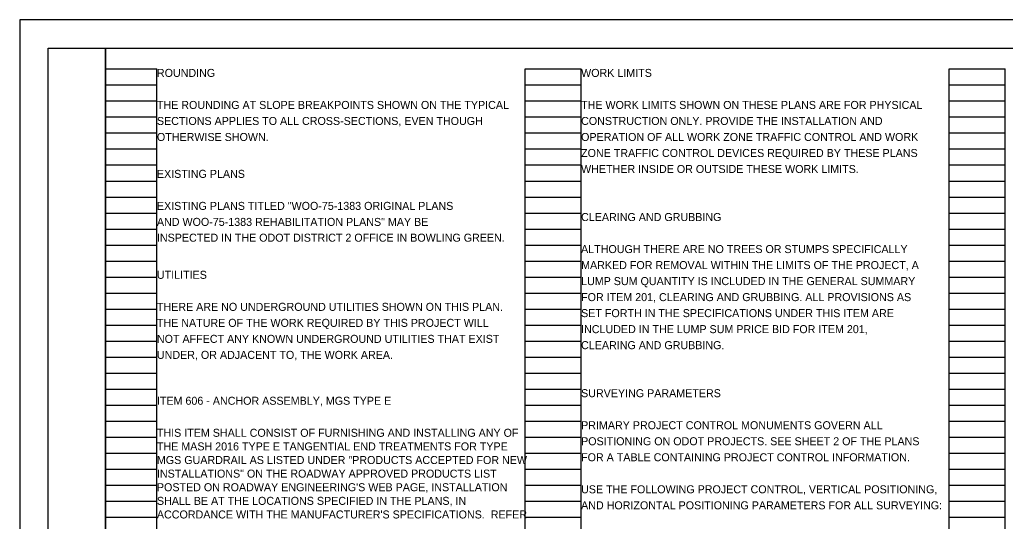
# Model space of a CAD drawing. Extents: x -19.6 to 34, y -1.8 to 22.
# Drawn here: x 0 to 17.24, y 13.23 to 22 of the extents above; entities that cross this region are included whole.
import ezdxf

# ---------------------------------------------------------------- set-up
doc = ezdxf.new("R2010")
doc.units = 0
for name, color, linetype in [('SH_Border', 7, 'Continuous'), ('SH_Cut_Line', 7, 'Continuous'), ('SH_Data', 7, 'Continuous'), ('SH_Text', 7, 'Continuous')]:
    doc.layers.add(name, color=color, linetype=linetype)

msp = doc.modelspace()

# ---------------------------------------------------------------- linework, layer by layer
at = {"layer": 'SH_Border'}
msp.add_lwpolyline([(0, 0), (34, 0), (34, 22), (0, 22)], close=True, dxfattribs=at)
at = {"layer": 'SH_Cut_Line'}
for points in [[(0.5, 21.5), (1.5, 21.5), (1.5, 0.5), (0.5, 0.5)], [(1.5, 21.5), (33.5, 21.5), (33.5, 0.5), (1.5, 0.5)]]:
    msp.add_lwpolyline(points, close=True, dxfattribs=at)
at = {"layer": 'SH_Data'}
for p, q in [((1.5, 0.98), (1.5, 21.14)), ((1.5, 21.14), (2.4, 21.14)), ((2.4, 0.98), (2.4, 21.14)), ((8.84, 0.98), (8.84, 21.14)), ((8.84, 21.14), (9.82, 21.14)), ((9.82, 0.98), (9.82, 21.14)), ((16.26, 0.98), (16.26, 21.14)), ((16.26, 21.14), (17.24, 21.14)), ((17.24, 0.98), (17.24, 21.14)), ((1.5, 20.86), (2.4, 20.86)), ((8.84, 20.86), (9.82, 20.86)), ((16.26, 20.86), (17.24, 20.86)), ((1.5, 20.58), (2.4, 20.58)), ((8.84, 20.58), (9.82, 20.58)), ((16.26, 20.58), (17.24, 20.58)), ((1.5, 20.3), (2.4, 20.3)), ((8.84, 20.3), (9.82, 20.3)), ((16.26, 20.3), (17.24, 20.3)), ((1.5, 20.02), (2.4, 20.02)), ((8.84, 20.02), (9.82, 20.02)), ((16.26, 20.02), (17.24, 20.02)), ((1.5, 19.74), (2.4, 19.74)), ((8.84, 19.74), (9.82, 19.74)), ((16.26, 19.74), (17.24, 19.74)), ((1.5, 19.46), (2.4, 19.46)), ((8.84, 19.46), (9.82, 19.46)), ((16.26, 19.46), (17.24, 19.46)), ((1.5, 19.18), (2.4, 19.18)), ((8.84, 19.18), (9.82, 19.18)), ((16.26, 19.18), (17.24, 19.18)), ((1.5, 18.9), (2.4, 18.9)), ((8.84, 18.9), (9.82, 18.9)), ((16.26, 18.9), (17.24, 18.9)), ((1.5, 18.62), (2.4, 18.62)), ((8.84, 18.62), (9.82, 18.62)), ((16.26, 18.62), (17.24, 18.62)), ((1.5, 18.34), (2.4, 18.34)), ((8.84, 18.34), (9.82, 18.34)), ((16.26, 18.34), (17.24, 18.34)), ((1.5, 18.06), (2.4, 18.06)), ((8.84, 18.06), (9.82, 18.06)), ((16.26, 18.06), (17.24, 18.06)), ((1.5, 17.78), (2.4, 17.78)), ((8.84, 17.78), (9.82, 17.78)), ((16.26, 17.78), (17.24, 17.78)), ((1.5, 17.5), (2.4, 17.5)), ((8.84, 17.5), (9.82, 17.5)), ((16.26, 17.5), (17.24, 17.5)), ((1.5, 17.22), (2.4, 17.22)), ((8.84, 17.22), (9.82, 17.22)), ((16.26, 17.22), (17.24, 17.22)), ((1.5, 16.94), (2.4, 16.94)), ((8.84, 16.94), (9.82, 16.94)), ((16.26, 16.94), (17.24, 16.94)), ((1.5, 16.66), (2.4, 16.66)), ((8.84, 16.66), (9.82, 16.66)), ((16.26, 16.66), (17.24, 16.66)), ((1.5, 16.38), (2.4, 16.38)), ((8.84, 16.38), (9.82, 16.38)), ((16.26, 16.38), (17.24, 16.38)), ((1.5, 16.1), (2.4, 16.1)), ((8.84, 16.1), (9.82, 16.1)), ((16.26, 16.1), (17.24, 16.1)), ((1.5, 15.82), (2.4, 15.82)), ((8.84, 15.82), (9.82, 15.82)), ((16.26, 15.82), (17.24, 15.82)), ((1.5, 15.54), (2.4, 15.54)), ((8.84, 15.54), (9.82, 15.54)), ((16.26, 15.54), (17.24, 15.54)), ((1.5, 15.26), (2.4, 15.26)), ((8.84, 15.26), (9.82, 15.26)), ((16.26, 15.26), (17.24, 15.26)), ((1.5, 14.98), (2.4, 14.98)), ((8.84, 14.98), (9.82, 14.98)), ((16.26, 14.98), (17.24, 14.98)), ((1.5, 14.7), (2.4, 14.7)), ((8.84, 14.7), (9.82, 14.7)), ((16.26, 14.7), (17.24, 14.7)), ((1.5, 14.42), (2.4, 14.42)), ((8.84, 14.42), (9.82, 14.42)), ((16.26, 14.42), (17.24, 14.42)), ((1.5, 14.14), (2.4, 14.14)), ((8.84, 14.14), (9.82, 14.14)), ((16.26, 14.14), (17.24, 14.14)), ((1.5, 13.86), (2.4, 13.86)), ((8.84, 13.86), (9.82, 13.86)), ((16.26, 13.86), (17.24, 13.86)), ((1.5, 13.58), (2.4, 13.58)), ((8.84, 13.58), (9.82, 13.58)), ((16.26, 13.58), (17.24, 13.58)), ((1.5, 13.3), (2.4, 13.3)), ((8.84, 13.3), (9.82, 13.3)), ((16.26, 13.3), (17.24, 13.3))]:
    msp.add_line(p, q, dxfattribs=at)

# ---------------------------------------------------------------- texts
at = {"layer": 'SH_Text'}
for s, p in [('ROUNDING', (2.4, 21)), ('WORK LIMITS', (9.82, 21)), ('THE ROUNDING AT SLOPE BREAKPOINTS SHOWN ON THE TYPICAL', (2.4, 20.44)), ('THE WORK LIMITS SHOWN ON THESE PLANS ARE FOR PHYSICAL', (9.82, 20.44)), ('SECTIONS APPLIES TO ALL CROSS-SECTIONS, EVEN THOUGH', (2.4, 20.16)), ('CONSTRUCTION ONLY. PROVIDE THE INSTALLATION AND', (9.82, 20.16)), ('OTHERWISE SHOWN.', (2.4, 19.88)), ('OPERATION OF ALL WORK ZONE TRAFFIC CONTROL AND WORK', (9.82, 19.88)), ('ZONE TRAFFIC CONTROL DEVICES REQUIRED BY THESE PLANS', (9.82, 19.6)), ('EXISTING PLANS', (2.4, 19.235)), ('WHETHER INSIDE OR OUTSIDE THESE WORK LIMITS.', (9.82, 19.32)), ('EXISTING PLANS TITLED "WOO-75-1383 ORIGINAL PLANS', (2.4, 18.675)), ('CLEARING AND GRUBBING', (9.82, 18.48)), ('AND WOO-75-1383 REHABILITATION PLANS" MAY BE', (2.4, 18.395)), ('INSPECTED IN THE ODOT DISTRICT 2 OFFICE IN BOWLING GREEN.', (2.4, 18.119)), ('ALTHOUGH THERE ARE NO TREES OR STUMPS SPECIFICALLY', (9.82, 17.92)), ('MARKED FOR REMOVAL WITHIN THE LIMITS OF THE PROJECT, A', (9.82, 17.64)), ('UTILITIES', (2.4, 17.47)), ('LUMP SUM QUANTITY IS INCLUDED IN THE GENERAL SUMMARY', (9.82, 17.36)), ('FOR ITEM 201, CLEARING AND GRUBBING. ALL PROVISIONS AS', (9.82, 17.08)), ('THERE ARE NO UNDERGROUND UTILITIES SHOWN ON THIS PLAN.', (2.4, 16.91)), ('SET FORTH IN THE SPECIFICATIONS UNDER THIS ITEM ARE', (9.82, 16.8)), ('THE NATURE OF THE WORK REQUIRED BY THIS PROJECT WILL', (2.4, 16.63)), ('INCLUDED IN THE LUMP SUM PRICE BID FOR ITEM 201,', (9.82, 16.52)), ('NOT AFFECT ANY KNOWN UNDERGROUND UTILITIES THAT EXIST', (2.4, 16.35)), ('CLEARING AND GRUBBING.', (9.82, 16.24)), ('UNDER, OR ADJACENT TO, THE WORK AREA.', (2.4, 16.07)), ('SURVEYING PARAMETERS', (9.82, 15.4)), ('ITEM 606 - ANCHOR ASSEMBLY, MGS TYPE E', (2.4, 15.268)), ('THIS ITEM SHALL CONSIST OF FURNISHING AND INSTALLING ANY OF ', (2.4, 14.708)), ('PRIMARY PROJECT CONTROL MONUMENTS GOVERN ALL', (9.82, 14.84)), ('POSITIONING ON ODOT PROJECTS. SEE SHEET 2 OF THE PLANS', (9.82, 14.56)), ('THE MASH 2016 TYPE E TANGENTIAL END TREATMENTS FOR TYPE ', (2.4, 14.47)), ('MGS GUARDRAIL AS LISTED UNDER "PRODUCTS ACCEPTED FOR NEW ', (2.4, 14.232)), ('FOR A TABLE CONTAINING PROJECT CONTROL INFORMATION.', (9.82, 14.28)), ('INSTALLATIONS" ON THE ROADWAY APPROVED PRODUCTS LIST ', (2.4, 13.994)), ("POSTED ON ROADWAY ENGINEERING'S WEB PAGE, INSTALLATION ", (2.4, 13.756)), ('USE THE FOLLOWING PROJECT CONTROL, VERTICAL POSITIONING,', (9.82, 13.72)), ('SHALL BE AT THE LOCATIONS SPECIFIED IN THE PLANS, IN ', (2.4, 13.518)), ('AND HORIZONTAL POSITIONING PARAMETERS FOR ALL SURVEYING:', (9.82, 13.44)), ("ACCORDANCE WITH THE MANUFACTURER'S SPECIFICATIONS.  REFER ", (2.4, 13.28))]:
    msp.add_text(s, height=0.14, dxfattribs=at).set_placement(p)

doc.saveas('drawing.dxf')
